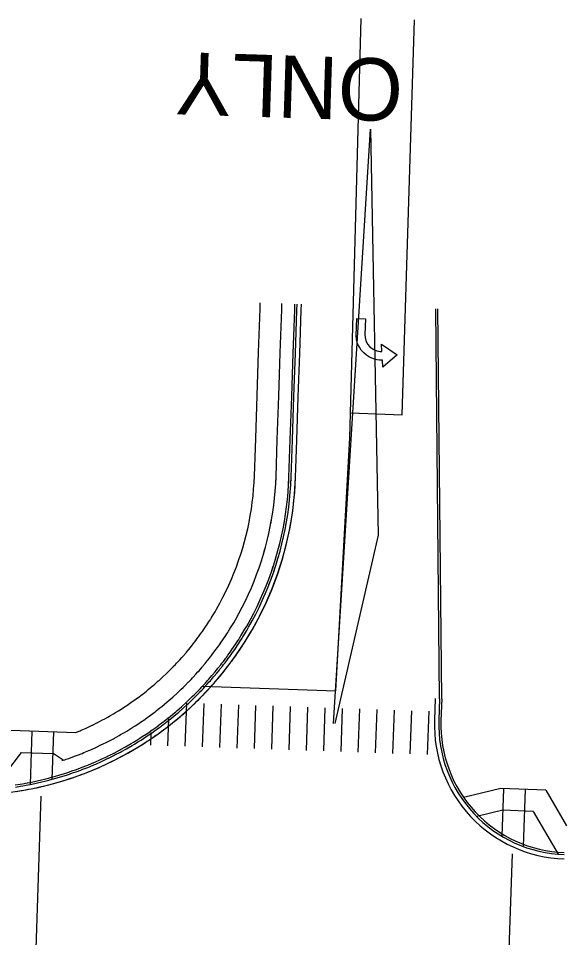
# Model space of a CAD drawing. Extents: x 979036 to 996074, y 1836928 to 1845163.
# Drawn here: x 992439.3 to 992566, y 1843908 to 1844120.3 of the extents above; entities that cross this region are included whole.
import ezdxf

# ---------------------------------------------------------------- set-up
doc = ezdxf.new("R2010")
doc.units = 0
for name, color, linetype in [('R_Proposed Road', 7, 'Continuous'), ('STRIPE_EXIST', 7, 'Continuous'), ('STRIPE_White Crosswalk', 7, 'Continuous'), ('STRIPE_White Stopbar', 7, 'Continuous'), ('STRIPE_White Turn Arrow', 7, 'Continuous'), ('STRIPE_White_6in', 7, 'Continuous'), ('STRIPE_White_ONLY', 7, 'Continuous'), ('STRIPE_Yellow Dbl 6in', 7, 'Continuous')]:
    doc.layers.add(name, color=color, linetype=linetype)

msp = doc.modelspace()

# ---------------------------------------------------------------- linework, layer by layer
at = {"layer": 'R_Proposed Road'}
for p, q in [((992536.61, 1843963.13), (992535.72, 1844053.22)), ((992537.11, 1843963.12), (992536.22, 1844053.2)), ((992536.61, 1843963.13), (992536.44, 1843958.14)), ((992537.11, 1843963.12), (992536.94, 1843958.12)), ((992437.6, 1843955.84), (992452.6, 1843955.33)), ((992442.08, 1843943.32), (992442.5, 1843955.67)), ((992447.12, 1843944.51), (992447.5, 1843955.5)), ((992436.38, 1843945.93), (992440.02, 1843950.75)), ((992440.02, 1843950.75), (992447.33, 1843950.51)), ((992449.63, 1843948.91), (992447.33, 1843950.51)), ((992550.74, 1843942.38), (992542.16, 1843940.34)), ((992561.17, 1843942.02), (992550.74, 1843942.38)), ((992551.41, 1843942.35), (992551.04, 1843931.36)), ((992556.41, 1843942.18), (992555.96, 1843929)), ((992561.17, 1843942.02), (992565.97, 1843933.78)), ((992551.24, 1843937.36), (992545.19, 1843935.92)), ((992558.24, 1843937.12), (992551.24, 1843937.36)), ((992558.24, 1843937.12), (992564.01, 1843927.21))]:
    msp.add_line(p, q, dxfattribs=at)
for points in [[(992493.84, 1844014.59), (992494.13, 1844023.23), (992494.47, 1844033.22), (992494.81, 1844043.22), (992495.16, 1844053.21), (992495.2, 1844054.6)], [(992496.13, 1843997.26), (992496.38, 1843998.13), (992496.79, 1843999.73), (992497.17, 1844001.34), (992497.51, 1844002.95), (992497.67, 1844003.77), (992497.68, 1844003.85), (992497.81, 1844004.58), (992498.08, 1844006.21), (992498.3, 1844007.84), (992498.49, 1844009.48), (992498.64, 1844011.13), (992498.76, 1844012.77), (992498.78, 1844013.14), (992498.83, 1844014.42), (992499.13, 1844023.06), (992499.47, 1844033.05), (992499.81, 1844043.05), (992500.15, 1844053.04), (992500.2, 1844054.43)], [(992497.03, 1843990.45), (992497.17, 1843990.8), (992497.75, 1843992.42), (992498.12, 1843993.5), (992498.3, 1843994.05), (992498.8, 1843995.69), (992499.27, 1843997.35), (992499.7, 1843999.01), (992500.1, 1844000.69), (992500.45, 1844002.37), (992500.62, 1844003.22), (992500.63, 1844003.3), (992500.77, 1844004.06), (992501.04, 1844005.76), (992501.28, 1844007.46), (992501.48, 1844009.17), (992501.64, 1844010.89), (992501.75, 1844012.6), (992501.77, 1844012.99), (992501.83, 1844014.32), (992502.13, 1844022.96), (992502.47, 1844032.95), (992502.81, 1844042.94), (992503.15, 1844052.94), (992503.2, 1844054.33)], [(992497.17, 1843989.42), (992497.63, 1843990.62), (992498.22, 1843992.25), (992498.59, 1843993.34), (992498.77, 1843993.89), (992499.28, 1843995.55), (992499.76, 1843997.22), (992500.19, 1843998.89), (992500.59, 1844000.58), (992500.94, 1844002.27), (992501.11, 1844003.13), (992501.12, 1844003.21), (992501.26, 1844003.98), (992501.54, 1844005.69), (992501.78, 1844007.4), (992501.97, 1844009.12), (992502.13, 1844010.85), (992502.25, 1844012.57), (992502.27, 1844012.96), (992502.33, 1844014.3), (992502.63, 1844022.94), (992502.97, 1844032.93), (992503.31, 1844042.93), (992503.65, 1844052.92), (992503.7, 1844054.31)], [(992449.37, 1843948.84), (992450.03, 1843949.06), (992450.34, 1843949.16), (992450.93, 1843949.36), (992451.51, 1843949.57), (992452.48, 1843949.92), (992452.97, 1843950.11), (992454.02, 1843950.52), (992454.4, 1843950.68), (992455.55, 1843951.16), (992455.82, 1843951.27), (992457.06, 1843951.82), (992457.21, 1843951.89), (992458.55, 1843952.53), (992458.58, 1843952.54), (992459.89, 1843953.19), (992459.93, 1843953.21), (992460.03, 1843953.26), (992461.26, 1843953.91), (992461.49, 1843954.03), (992462.56, 1843954.62), (992462.93, 1843954.84), (992463.83, 1843955.36), (992464.35, 1843955.68), (992465.08, 1843956.12), (992465.76, 1843956.55), (992466.3, 1843956.9), (992467.14, 1843957.45), (992467.5, 1843957.69), (992468.5, 1843958.38), (992468.66, 1843958.5), (992469.5, 1843959.1), (992469.8, 1843959.32), (992469.84, 1843959.35), (992470.91, 1843960.15), (992471.16, 1843960.34), (992471.99, 1843961), (992472.45, 1843961.37), (992473.04, 1843961.85), (992473.72, 1843962.42), (992474.06, 1843962.72), (992474.97, 1843963.51), (992475.05, 1843963.58), (992476.01, 1843964.45), (992476.19, 1843964.62), (992476.93, 1843965.33), (992477.38, 1843965.76), (992477.82, 1843966.2), (992478.55, 1843966.93), (992478.68, 1843967.06), (992479.2, 1843967.61), (992479.5, 1843967.93), (992479.69, 1843968.13), (992480.29, 1843968.78), (992480.8, 1843969.35), (992481.04, 1843969.62), (992481.76, 1843970.45), (992481.88, 1843970.59), (992482.44, 1843971.26), (992482.94, 1843971.86), (992483.09, 1843972.05), (992483.7, 1843972.82), (992483.96, 1843973.16), (992484.27, 1843973.56), (992484.8, 1843974.27), (992484.95, 1843974.48), (992485.3, 1843974.95), (992485.76, 1843975.59), (992485.92, 1843975.82), (992486.18, 1843976.19), (992486.56, 1843976.74), (992486.85, 1843977.18), (992486.9, 1843977.25), (992487.2, 1843977.71), (992487.46, 1843978.11), (992487.68, 1843978.46), (992487.75, 1843978.57), (992487.87, 1843978.75), (992488.01, 1843978.97), (992488.11, 1843979.13), (992488.17, 1843979.23), (992488.19, 1843979.26), (992488.62, 1843979.97), (992489.06, 1843980.71), (992489.46, 1843981.39), (992490.26, 1843982.84), (992491.03, 1843984.3), (992491.76, 1843985.78), (992492.46, 1843987.27), (992493.13, 1843988.78), (992493.76, 1843990.31), (992494.36, 1843991.85), (992494.92, 1843993.4), (992495.44, 1843994.97), (992495.93, 1843996.54), (992496.38, 1843998.13), (992496.79, 1843999.73), (992497.17, 1844001.34), (992497.51, 1844002.95), (992497.81, 1844004.58), (992498.08, 1844006.21), (992498.3, 1844007.84), (992498.49, 1844009.48), (992498.64, 1844011.13), (992498.76, 1844012.77), (992498.83, 1844014.42)], [(992452.51, 1843955.31), (992453.58, 1843955.75), (992453.83, 1843955.86), (992454.98, 1843956.37), (992455.13, 1843956.44), (992456.37, 1843957.03), (992456.4, 1843957.04), (992457.61, 1843957.64), (992457.66, 1843957.66), (992457.75, 1843957.71), (992458.89, 1843958.31), (992459.1, 1843958.43), (992460.1, 1843958.98), (992460.45, 1843959.18), (992461.28, 1843959.66), (992461.77, 1843959.96), (992462.44, 1843960.37), (992463.07, 1843960.76), (992463.58, 1843961.09), (992464.36, 1843961.6), (992464.69, 1843961.83), (992465.63, 1843962.47), (992465.78, 1843962.58), (992466.55, 1843963.14), (992466.84, 1843963.34), (992466.87, 1843963.37), (992467.87, 1843964.12), (992468.1, 1843964.3), (992468.87, 1843964.91), (992469.3, 1843965.25), (992469.85, 1843965.7), (992470.48, 1843966.23), (992470.8, 1843966.5), (992471.64, 1843967.24), (992471.72, 1843967.31), (992472.61, 1843968.12), (992472.77, 1843968.28), (992473.46, 1843968.93), (992473.88, 1843969.34), (992474.29, 1843969.74), (992474.97, 1843970.42), (992475.09, 1843970.55), (992475.58, 1843971.05), (992475.85, 1843971.35), (992476.03, 1843971.54), (992476.59, 1843972.14), (992477.06, 1843972.67), (992477.29, 1843972.93), (992477.96, 1843973.7), (992478.07, 1843973.83), (992478.59, 1843974.45), (992479.05, 1843975.01), (992479.19, 1843975.19), (992479.76, 1843975.9), (992480, 1843976.22), (992480.29, 1843976.59), (992480.79, 1843977.25), (992480.93, 1843977.44), (992481.25, 1843977.88), (992481.67, 1843978.48), (992481.82, 1843978.69), (992482.06, 1843979.03), (992482.42, 1843979.55), (992482.69, 1843979.96), (992482.74, 1843980.02), (992483.02, 1843980.45), (992483.26, 1843980.82), (992483.47, 1843981.15), (992483.53, 1843981.24), (992483.64, 1843981.41), (992483.77, 1843981.62), (992483.86, 1843981.77), (992483.92, 1843981.86), (992483.94, 1843981.89), (992484.34, 1843982.55), (992484.74, 1843983.23), (992485.11, 1843983.87), (992485.86, 1843985.22), (992486.58, 1843986.58), (992487.26, 1843987.95), (992487.91, 1843989.34), (992488.53, 1843990.75), (992489.12, 1843992.17), (992489.67, 1843993.6), (992490.19, 1843995.04), (992490.68, 1843996.5), (992491.13, 1843997.97), (992491.55, 1843999.44), (992491.94, 1844000.93), (992492.29, 1844002.42), (992492.6, 1844003.93), (992492.89, 1844005.44), (992493.13, 1844006.95), (992493.34, 1844008.47), (992493.52, 1844010), (992493.66, 1844011.53), (992493.77, 1844013.06), (992493.84, 1844014.59)], [(992438.58, 1843943.22), (992439.72, 1843943.4), (992440.28, 1843943.5), (992441.37, 1843943.7), (992441.41, 1843943.71), (992441.97, 1843943.82), (992443.02, 1843944.03), (992443.65, 1843944.17), (992444.64, 1843944.4), (992445.33, 1843944.57), (992446.26, 1843944.8), (992446.99, 1843945), (992447.85, 1843945.24), (992448.64, 1843945.47), (992449.43, 1843945.71), (992450.29, 1843945.98), (992450.98, 1843946.21), (992451.3, 1843946.32), (992451.92, 1843946.53), (992452.52, 1843946.74), (992453.54, 1843947.12), (992454.04, 1843947.31), (992455.14, 1843947.74), (992455.54, 1843947.9), (992456.73, 1843948.4), (992457.01, 1843948.52), (992458.3, 1843949.09), (992458.46, 1843949.17), (992459.86, 1843949.83), (992459.89, 1843949.84), (992461.25, 1843950.52), (992461.3, 1843950.54), (992461.4, 1843950.59), (992462.68, 1843951.27), (992462.92, 1843951.4), (992464.03, 1843952.01), (992464.42, 1843952.24), (992465.36, 1843952.78), (992465.91, 1843953.11), (992466.66, 1843953.57), (992467.37, 1843954.01), (992467.94, 1843954.38), (992468.81, 1843954.95), (992469.18, 1843955.2), (992470.23, 1843955.93), (992470.4, 1843956.05), (992471.27, 1843956.67), (992471.58, 1843956.9), (992471.62, 1843956.93), (992472.74, 1843957.77), (992473, 1843957.97), (992473.87, 1843958.65), (992474.34, 1843959.04), (992474.96, 1843959.55), (992475.67, 1843960.14), (992476.02, 1843960.44), (992476.96, 1843961.27), (992477.05, 1843961.35), (992478.05, 1843962.25), (992478.23, 1843962.43), (992479.01, 1843963.16), (992479.48, 1843963.62), (992479.94, 1843964.07), (992480.69, 1843964.84), (992480.83, 1843964.98), (992481.37, 1843965.54), (992481.69, 1843965.87), (992481.88, 1843966.08), (992482.51, 1843966.76), (992483.04, 1843967.35), (992483.29, 1843967.64), (992484.04, 1843968.5), (992484.17, 1843968.65), (992484.75, 1843969.35), (992485.27, 1843969.98), (992485.42, 1843970.17), (992486.06, 1843970.97), (992486.33, 1843971.33), (992486.66, 1843971.74), (992487.21, 1843972.48), (992487.37, 1843972.7), (992487.73, 1843973.19), (992488.21, 1843973.86), (992488.37, 1843974.1), (992488.64, 1843974.48), (992489.04, 1843975.06), (992489.35, 1843975.52), (992489.4, 1843975.59), (992489.71, 1843976.07), (992489.98, 1843976.49), (992490.21, 1843976.85), (992490.28, 1843976.96), (992490.4, 1843977.15), (992490.55, 1843977.38), (992490.66, 1843977.55), (992490.72, 1843977.65), (992490.74, 1843977.69), (992491.19, 1843978.42), (992491.65, 1843979.19), (992492.06, 1843979.91), (992492.9, 1843981.41), (992493.7, 1843982.93), (992494.46, 1843984.47), (992495.19, 1843986.03), (992495.89, 1843987.6), (992496.55, 1843989.19), (992497.17, 1843990.8), (992497.75, 1843992.42), (992498.3, 1843994.05), (992498.8, 1843995.69), (992499.27, 1843997.35), (992499.7, 1843999.01), (992500.1, 1844000.69), (992500.45, 1844002.37), (992500.77, 1844004.06), (992501.04, 1844005.76), (992501.28, 1844007.46), (992501.48, 1844009.17), (992501.64, 1844010.89), (992501.75, 1844012.6), (992501.83, 1844014.32)], [(992438.65, 1843942.73), (992439.8, 1843942.91), (992440.36, 1843943.01), (992441.47, 1843943.21), (992441.5, 1843943.21), (992442.07, 1843943.33), (992443.12, 1843943.54), (992443.76, 1843943.68), (992444.76, 1843943.92), (992445.45, 1843944.08), (992446.38, 1843944.32), (992447.12, 1843944.52), (992447.99, 1843944.76), (992448.79, 1843944.99), (992449.57, 1843945.23), (992450.44, 1843945.51), (992451.14, 1843945.74), (992451.46, 1843945.84), (992452.08, 1843946.06), (992452.69, 1843946.27), (992453.71, 1843946.65), (992454.22, 1843946.84), (992455.33, 1843947.27), (992455.72, 1843947.44), (992456.93, 1843947.94), (992457.21, 1843948.06), (992458.51, 1843948.64), (992458.67, 1843948.71), (992460.08, 1843949.38), (992460.11, 1843949.39), (992461.48, 1843950.07), (992461.52, 1843950.1), (992461.63, 1843950.15), (992462.91, 1843950.83), (992463.16, 1843950.96), (992464.28, 1843951.58), (992464.67, 1843951.8), (992465.61, 1843952.35), (992466.16, 1843952.68), (992466.93, 1843953.15), (992467.64, 1843953.59), (992468.21, 1843953.96), (992469.09, 1843954.54), (992469.46, 1843954.79), (992470.52, 1843955.52), (992470.69, 1843955.64), (992471.56, 1843956.27), (992471.88, 1843956.5), (992471.92, 1843956.53), (992473.04, 1843957.38), (992473.3, 1843957.58), (992474.18, 1843958.26), (992474.66, 1843958.65), (992475.28, 1843959.16), (992475.99, 1843959.76), (992476.35, 1843960.07), (992477.3, 1843960.9), (992477.38, 1843960.98), (992478.39, 1843961.89), (992478.58, 1843962.06), (992479.36, 1843962.8), (992479.83, 1843963.26), (992480.29, 1843963.72), (992481.05, 1843964.49), (992481.19, 1843964.63), (992481.74, 1843965.2), (992482.05, 1843965.53), (992482.25, 1843965.74), (992482.88, 1843966.43), (992483.41, 1843967.02), (992483.67, 1843967.31), (992484.42, 1843968.18), (992484.55, 1843968.33), (992485.14, 1843969.03), (992485.66, 1843969.66), (992485.81, 1843969.86), (992486.45, 1843970.66), (992486.73, 1843971.02), (992487.05, 1843971.44), (992487.61, 1843972.19), (992487.77, 1843972.4), (992488.13, 1843972.9), (992488.61, 1843973.57), (992488.78, 1843973.81), (992489.05, 1843974.2), (992489.45, 1843974.78), (992489.76, 1843975.24), (992489.81, 1843975.31), (992490.13, 1843975.79), (992490.4, 1843976.22), (992490.64, 1843976.58), (992490.71, 1843976.69), (992490.83, 1843976.88), (992490.98, 1843977.12), (992491.08, 1843977.29), (992491.14, 1843977.39), (992491.17, 1843977.42), (992491.62, 1843978.16), (992492.08, 1843978.94), (992492.49, 1843979.66), (992493.34, 1843981.17), (992494.14, 1843982.7), (992494.91, 1843984.25), (992495.65, 1843985.82), (992496.35, 1843987.41), (992497.01, 1843989.01), (992497.63, 1843990.62), (992498.22, 1843992.25), (992498.77, 1843993.89), (992499.28, 1843995.55), (992499.76, 1843997.22), (992500.19, 1843998.89), (992500.59, 1844000.58), (992500.94, 1844002.27), (992501.26, 1844003.98), (992501.54, 1844005.69), (992501.78, 1844007.4), (992501.97, 1844009.12), (992502.13, 1844010.85), (992502.25, 1844012.57), (992502.33, 1844014.3)]]:
    msp.add_lwpolyline(points, dxfattribs=at)
for centre, radius, start, end in [((992427.39, 1844016.86), 76, 268.0557, 358.0437), ((992566.43, 1843957.11), 30, 178.0437, 268.0557), ((992566.43, 1843957.11), 29.5, 178.0437, 268.0557)]:
    msp.add_arc(centre, radius, start, end, dxfattribs=at)
at = {"layer": 'STRIPE_EXIST'}
for p, q in [((992535.62, 1843963.17), (992535.44, 1843958.17)), ((992444.51, 1843940.63), (992442.87, 1843890.72)), ((992553.36, 1843927.31), (992552.41, 1843898.33))]:
    msp.add_line(p, q, dxfattribs=at)
for points in [[(992512.12, 1843957.44), (992520.67, 1844094.69), (992522.43, 1844000.89), (992512.45, 1843957.42)], [(992497.43, 1843987.39), (992497.95, 1843988.63), (992498.58, 1843990.27), (992499.18, 1843991.92), (992499.55, 1843993.03), (992499.73, 1843993.59), (992500.25, 1843995.26), (992500.73, 1843996.95), (992501.17, 1843998.65), (992501.57, 1844000.36), (992501.93, 1844002.08), (992502.1, 1844002.94), (992502.12, 1844003.03), (992502.25, 1844003.8), (992502.54, 1844005.54), (992502.78, 1844007.27), (992502.98, 1844009.02), (992503.14, 1844010.77), (992503.26, 1844012.52), (992503.28, 1844012.91), (992503.34, 1844014.27), (992503.64, 1844022.9), (992503.98, 1844032.9), (992504.32, 1844042.89), (992504.66, 1844052.89), (992504.71, 1844054.28)], [(992438.81, 1843941.73), (992439.97, 1843941.91), (992440.54, 1843942.01), (992441.66, 1843942.22), (992441.69, 1843942.22), (992442.26, 1843942.34), (992443.33, 1843942.56), (992443.98, 1843942.7), (992444.99, 1843942.93), (992445.69, 1843943.1), (992446.64, 1843943.34), (992447.39, 1843943.54), (992448.26, 1843943.79), (992449.08, 1843944.03), (992449.87, 1843944.27), (992450.75, 1843944.55), (992451.46, 1843944.78), (992451.79, 1843944.89), (992452.42, 1843945.1), (992453.03, 1843945.32), (992454.07, 1843945.7), (992454.58, 1843945.9), (992455.7, 1843946.34), (992456.11, 1843946.5), (992457.32, 1843947.01), (992457.61, 1843947.13), (992458.93, 1843947.72), (992459.09, 1843947.79), (992460.52, 1843948.47), (992460.55, 1843948.48), (992461.94, 1843949.17), (992461.98, 1843949.2), (992462.09, 1843949.25), (992463.39, 1843949.94), (992463.64, 1843950.07), (992464.77, 1843950.7), (992465.17, 1843950.93), (992466.13, 1843951.48), (992466.69, 1843951.82), (992467.46, 1843952.29), (992468.18, 1843952.74), (992468.76, 1843953.11), (992469.65, 1843953.7), (992470.03, 1843953.95), (992471.1, 1843954.69), (992471.27, 1843954.81), (992472.16, 1843955.45), (992472.48, 1843955.69), (992472.52, 1843955.72), (992473.66, 1843956.58), (992473.92, 1843956.78), (992474.81, 1843957.47), (992475.3, 1843957.87), (992475.92, 1843958.38), (992476.65, 1843958.99), (992477.01, 1843959.3), (992477.97, 1843960.14), (992478.06, 1843960.22), (992479.07, 1843961.15), (992479.27, 1843961.33), (992480.06, 1843962.07), (992480.53, 1843962.54), (992481, 1843963), (992481.77, 1843963.78), (992481.91, 1843963.92), (992482.47, 1843964.5), (992482.79, 1843964.84), (992482.99, 1843965.05), (992483.63, 1843965.75), (992484.17, 1843966.35), (992484.43, 1843966.64), (992485.19, 1843967.52), (992485.32, 1843967.67), (992485.91, 1843968.38), (992486.44, 1843969.03), (992486.6, 1843969.23), (992487.25, 1843970.04), (992487.53, 1843970.4), (992487.86, 1843970.83), (992488.42, 1843971.58), (992488.59, 1843971.8), (992488.95, 1843972.31), (992489.44, 1843972.99), (992489.61, 1843973.23), (992489.89, 1843973.62), (992490.29, 1843974.21), (992490.6, 1843974.68), (992490.65, 1843974.75), (992490.97, 1843975.24), (992491.25, 1843975.67), (992491.49, 1843976.04), (992491.56, 1843976.15), (992491.68, 1843976.34), (992491.83, 1843976.58), (992491.94, 1843976.75), (992492, 1843976.86), (992492.02, 1843976.89), (992492.48, 1843977.64), (992492.95, 1843978.42), (992493.37, 1843979.16), (992494.22, 1843980.69), (992495.04, 1843982.24), (992495.82, 1843983.81), (992496.57, 1843985.4), (992497.28, 1843987.01), (992497.95, 1843988.63), (992498.58, 1843990.27), (992499.18, 1843991.92), (992499.73, 1843993.59), (992500.25, 1843995.26), (992500.73, 1843996.95), (992501.17, 1843998.65), (992501.57, 1844000.36), (992501.93, 1844002.08), (992502.25, 1844003.8), (992502.54, 1844005.54), (992502.78, 1844007.27), (992502.98, 1844009.02), (992503.14, 1844010.77), (992503.26, 1844012.52), (992503.34, 1844014.27)]]:
    msp.add_lwpolyline(points, dxfattribs=at)
msp.add_arc((992566.43, 1843957.11), 31, 178.0437, 268.0557, dxfattribs=at)
at = {"layer": 'STRIPE_White Crosswalk'}
for p, q in [((992478.13, 1843962.15), (992477.79, 1843952.16)), ((992482.13, 1843962.02), (992481.79, 1843952.02)), ((992486.13, 1843961.88), (992485.79, 1843951.89)), ((992490.13, 1843961.74), (992489.79, 1843951.75)), ((992494.12, 1843961.61), (992493.78, 1843951.61)), ((992498.12, 1843961.47), (992497.78, 1843951.48)), ((992502.12, 1843961.33), (992501.78, 1843951.34)), ((992506.12, 1843961.2), (992505.78, 1843951.2)), ((992510.12, 1843961.06), (992509.77, 1843951.07)), ((992514.11, 1843960.92), (992513.77, 1843950.93)), ((992518.11, 1843960.79), (992517.77, 1843950.79)), ((992522.11, 1843960.65), (992521.77, 1843950.66)), ((992526.11, 1843960.51), (992525.76, 1843950.52)), ((992530.1, 1843960.38), (992529.76, 1843950.38)), ((992534.1, 1843960.24), (992533.76, 1843950.25)), ((992474.01, 1843958.52), (992473.79, 1843952.29)), ((992469.9, 1843955.33), (992469.8, 1843952.43))]:
    msp.add_line(p, q, dxfattribs=at)
at = {"layer": 'STRIPE_White Stopbar'}
for p, q in [((992516.03, 1844029.16), (992527.94, 1844028.75)), ((992481.82, 1843966.03), (992512.68, 1843964.97))]:
    msp.add_line(p, q, dxfattribs=at)
at = {"layer": 'STRIPE_White Turn Arrow'}
msp.add_lwpolyline([(992523.18, 1844045.03), (992526.79, 1844042.59), (992523.51, 1844039.72), (992523.41, 1844041.38), (992522.74, 1844041.39), (992522.17, 1844041.45), (992521.37, 1844041.64), (992520.44, 1844042.04), (992519.73, 1844042.48), (992519.15, 1844043.04), (992518.48, 1844043.69), (992518.1, 1844044.39), (992517.69, 1844045.15), (992517.46, 1844046.1), (992517.33, 1844047.09), (992517.52, 1844050.98), (992519.53, 1844050.89), (992519.38, 1844047.3), (992519.41, 1844046.61), (992519.61, 1844045.87), (992519.96, 1844045.08), (992520.51, 1844044.42), (992520.8, 1844044.19), (992521.41, 1844043.8), (992522.16, 1844043.53), (992522.89, 1844043.39), (992523.28, 1844043.37)], close=True, dxfattribs=at)
at = {"layer": 'STRIPE_White_6in'}
for p, q in [((992515.88, 1844023.43), (992518.5, 1844120.32)), ((992512.68, 1843964.97), (992515.88, 1844023.51))]:
    msp.add_line(p, q, dxfattribs=at)
at = {"layer": 'STRIPE_Yellow Dbl 6in'}
msp.add_line((992527.94, 1844028.75), (992530.83, 1844119.99), dxfattribs=at)

# ---------------------------------------------------------------- texts
at = {"layer": 'STRIPE_White_ONLY'}
msp.add_text('ONLY', height=14.4, rotation=178.1709, dxfattribs=at).set_placement((992528.35, 1844110.89))

doc.saveas('drawing.dxf')
